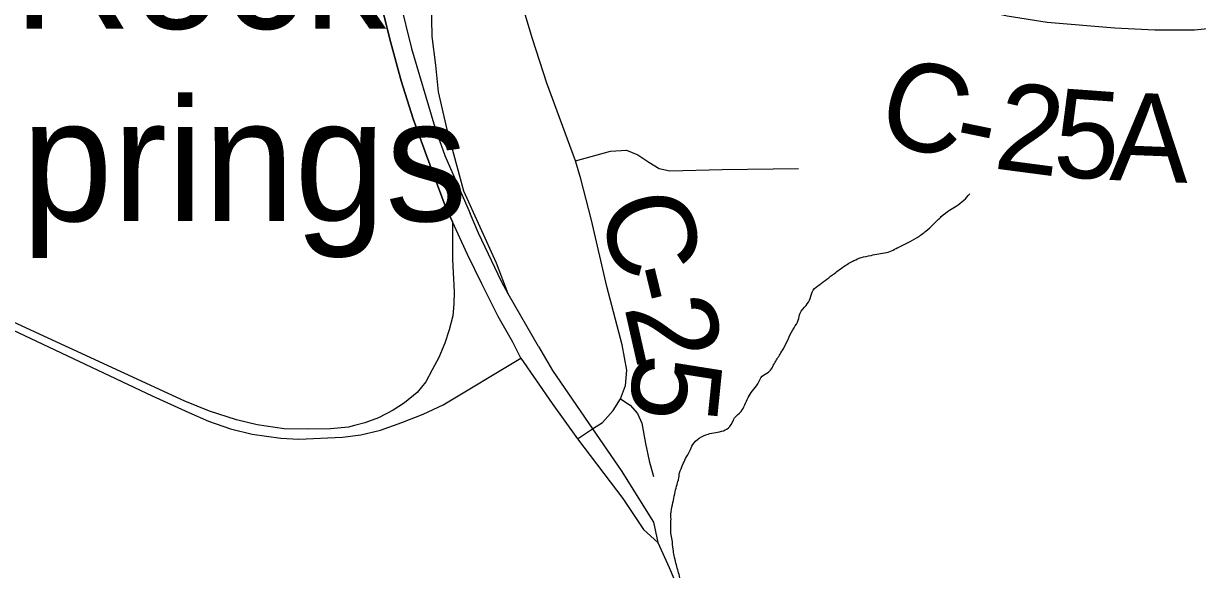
# Model space of a CAD drawing. Extents: x -20.2 to 34, y 0 to 22.
# Drawn here: x 5.177 to 5.935, y 15.58 to 15.933 of the extents above; entities that cross this region are included whole.
import ezdxf

# ---------------------------------------------------------------- set-up
doc = ezdxf.new("R2010")
doc.units = 0
for name, color, linetype in [('GM_X_County_Road', 7, 'Continuous'), ('GM_X_County_Road_Text', 7, 'Continuous'), ('GM_X_Interchange_Ramps', 7, 'Continuous'), ('GM_X_Minor_River', 7, 'Continuous'), ('GM_X_State_Route', 7, 'Continuous'), ('GM_X_Township_Road', 7, 'Continuous'), ('GM_X_Unincorporated_Text', 7, 'Continuous'), ('GM_X_US_Route', 7, 'Continuous')]:
    doc.layers.add(name, color=color, linetype=linetype)

msp = doc.modelspace()

# ---------------------------------------------------------------- linework, layer by layer
at = {"layer": 'GM_X_County_Road'}
for points in [[(5.75523, 15.95181), (5.77883, 15.94516), (5.81245, 15.93751), (5.8382, 15.93346), (5.88202, 15.92985), (5.8949, 15.92921), (5.90776, 15.92857), (5.9333, 15.92857), (5.9567, 15.93091), (5.97393, 15.93495), (6.04638, 15.95554)], [(5.53502, 15.66458), (5.54482, 15.67097), (5.55116, 15.67512), (5.55818, 15.68291), (5.56285, 15.69044), (5.56597, 15.69903), (5.56701, 15.7089), (5.5639, 15.72527), (5.55403, 15.76293), (5.54415, 15.80557), (5.53713, 15.83234), (5.53375, 15.84403), (5.51528, 15.89407), (5.50607, 15.92261), (5.50054, 15.94048)]]:
    msp.add_lwpolyline(points, dxfattribs=at)
at = {"layer": 'GM_X_Interchange_Ramps'}
msp.add_lwpolyline([(5.49038, 15.75812), (5.4828, 15.77801), (5.46179, 15.82446), (5.4509, 15.8641), (5.44535, 15.88847), (5.44363, 15.90567), (5.44133, 15.92417), (5.44076, 15.94714), (5.44092, 15.96778), (5.44274, 15.99016), (5.44484, 16.01367), (5.44575, 16.02546)], dxfattribs=at)
at = {"layer": 'GM_X_Minor_River'}
for points in [[(5.60098, 15.64268), (5.60292, 15.64761), (5.60485, 15.65176), (5.60754, 15.65668), (5.60947, 15.66084), (5.61367, 15.66498), (5.61938, 15.66759), (5.62926, 15.66979), (5.63346, 15.67242), (5.63654, 15.67809), (5.64074, 15.68223), (5.64305, 15.68639), (5.64805, 15.69546), (5.6515, 15.69999), (5.6542, 15.7049), (5.65839, 15.70753), (5.66261, 15.71395), (5.66645, 15.71999), (5.66876, 15.72414), (5.67493, 15.73624), (5.67762, 15.74116), (5.67879, 15.7457), (5.68263, 15.75061), (5.68532, 15.75514), (5.68725, 15.76044), (5.69146, 15.7642), (5.69603, 15.76758), (5.701, 15.77134), (5.7071, 15.77585), (5.71358, 15.77959), (5.71815, 15.78146), (5.72461, 15.78292), (5.72955, 15.78402), (5.73449, 15.78474), (5.74287, 15.78847), (5.7482, 15.79109), (5.7543, 15.79446), (5.76002, 15.79859), (5.76499, 15.80311), (5.76996, 15.808), (5.7753, 15.81213), (5.77949, 15.81476), (5.78446, 15.81852), (5.78828, 15.82266)], [(5.75291, 15.15939), (5.74953, 15.16435), (5.74087, 15.17315), (5.73824, 15.17735), (5.73486, 15.18193), (5.73187, 15.18727), (5.72735, 15.193), (5.72323, 15.1991), (5.72022, 15.2033), (5.71685, 15.20826), (5.71423, 15.2136), (5.71237, 15.21817), (5.71013, 15.22312), (5.70752, 15.22998), (5.70566, 15.23455), (5.70342, 15.23988), (5.70194, 15.24483), (5.7016, 15.24939), (5.70201, 15.25394), (5.70243, 15.25925), (5.70284, 15.26342), (5.70365, 15.27025), (5.70482, 15.27479), (5.70562, 15.27972), (5.70755, 15.28389), (5.70797, 15.28882), (5.70724, 15.29376), (5.70425, 15.29986), (5.69974, 15.30482), (5.69483, 15.3079), (5.68991, 15.31022), (5.68386, 15.31254), (5.67894, 15.31448), (5.67365, 15.31756), (5.66875, 15.32177), (5.66499, 15.32636), (5.66313, 15.33131), (5.66165, 15.33587), (5.65978, 15.34044), (5.65792, 15.34539), (5.65644, 15.34996), (5.65533, 15.35414), (5.65423, 15.35871), (5.65275, 15.36403), (5.65165, 15.36898), (5.65093, 15.3743), (5.65021, 15.37886), (5.6491, 15.38304), (5.64838, 15.3876), (5.64728, 15.39255), (5.6458, 15.39863), (5.6447, 15.40282), (5.64321, 15.40738), (5.64249, 15.41232), (5.64214, 15.4165), (5.64142, 15.42068), (5.64069, 15.42525), (5.63886, 15.43361), (5.63664, 15.44084), (5.63553, 15.44503), (5.63406, 15.45149), (5.63221, 15.45758), (5.63, 15.46671), (5.62814, 15.47166), (5.62742, 15.47698), (5.62594, 15.48116), (5.62483, 15.48535), (5.62412, 15.49105), (5.62263, 15.49524), (5.62115, 15.50094), (5.61967, 15.50551), (5.61856, 15.50969), (5.61708, 15.51426), (5.61598, 15.51882), (5.61375, 15.52453), (5.61302, 15.52871), (5.61004, 15.53595), (5.60893, 15.54013), (5.60821, 15.5447), (5.60636, 15.55192), (5.60526, 15.55611), (5.6034, 15.56143), (5.60268, 15.56638), (5.60158, 15.5717), (5.60085, 15.57588), (5.59864, 15.58425), (5.59754, 15.58919), (5.59681, 15.59337), (5.5961, 15.59945), (5.59537, 15.60363), (5.59544, 15.61274), (5.59548, 15.6173), (5.59666, 15.62336), (5.59784, 15.62904), (5.59902, 15.63397), (5.60019, 15.63814), (5.60098, 15.64268)]]:
    msp.add_spline(points, degree=3, dxfattribs=at)
at = {"layer": 'GM_X_State_Route'}
for points in [[(5.4332, 15.85923), (5.42891, 15.87114), (5.42133, 15.89552), (5.41467, 15.92013), (5.40903, 15.94217), (5.40544, 15.95858), (5.39319, 16.03068), (5.39075, 16.045), (5.38875, 16.0602)], [(5.45441, 15.8045), (5.44954, 15.81501), (5.43749, 15.84732), (5.4332, 15.85923)], [(5.49853, 15.71665), (5.49331, 15.72691), (5.48379, 15.74352), (5.47338, 15.76451), (5.46415, 15.78348), (5.45441, 15.8045)], [(5.50998, 15.72423), (5.49038, 15.75812), (5.486, 15.76597), (5.47127, 15.79731), (5.46575, 15.80998)], [(5.12688, 15.75529), (5.2604, 15.69228), (5.28423, 15.68152), (5.29696, 15.67596), (5.31099, 15.67106), (5.32504, 15.66747), (5.34364, 15.66486), (5.35507, 15.66421), (5.38347, 15.66551), (5.39522, 15.66715), (5.40795, 15.67009), (5.42167, 15.67498), (5.43553, 15.68037), (5.44844, 15.68641), (5.49853, 15.71665)], [(5.50998, 15.72423), (5.51898, 15.70865), (5.54482, 15.67097), (5.56332, 15.64399), (5.58417, 15.61069), (5.58697, 15.59754)], [(5.49853, 15.71665), (5.5187, 15.68728), (5.53502, 15.66458)], [(5.53502, 15.66458), (5.56438, 15.62593), (5.57776, 15.60593), (5.58697, 15.59754)], [(5.58697, 15.59754), (5.59436, 15.58159), (5.60094, 15.56581), (5.6062, 15.55052), (5.61196, 15.52997), (5.61689, 15.50892), (5.63094, 15.42707), (5.63429, 15.40897), (5.64013, 15.38613), (5.64376, 15.37025), (5.64973, 15.35079), (5.65586, 15.33217)]]:
    msp.add_lwpolyline(points, dxfattribs=at)
at = {"layer": 'GM_X_Township_Road'}
for points in [[(5.53375, 15.84403), (5.55636, 15.85027), (5.56676, 15.85079), (5.57395, 15.84793), (5.58118, 15.84304), (5.58777, 15.839), (5.59458, 15.8375), (5.62841, 15.83836), (5.67778, 15.83901)], [(5.56285, 15.69044), (5.56909, 15.68629), (5.57377, 15.68083), (5.57663, 15.67459), (5.57897, 15.6616), (5.58131, 15.65043), (5.58417, 15.64029)]]:
    msp.add_lwpolyline(points, dxfattribs=at)
at = {"layer": 'GM_X_US_Route'}
for points in [[(5.32948, 16.4963), (5.33321, 16.47263), (5.33614, 16.45673), (5.35628, 16.33081), (5.36333, 16.28673), (5.38001, 16.19003), (5.40354, 16.04385), (5.40604, 16.02948), (5.42042, 15.94697), (5.42784, 15.91649), (5.44228, 15.86788), (5.44498, 15.86017)], [(5.38875, 16.0602), (5.39075, 16.045), (5.39319, 16.03068), (5.40544, 15.95858), (5.40903, 15.94217), (5.41467, 15.92013), (5.42133, 15.89552), (5.42891, 15.87114), (5.4332, 15.85923)], [(5.4332, 15.85923), (5.43749, 15.84732), (5.44954, 15.81501), (5.45441, 15.8045)], [(5.44498, 15.86017), (5.44949, 15.84732), (5.46575, 15.80998)], [(5.45441, 15.8045), (5.45433, 15.78026), (5.45554, 15.75933), (5.45532, 15.75144), (5.45464, 15.74399), (5.45216, 15.73498), (5.44946, 15.72619), (5.44563, 15.71695), (5.44135, 15.70905), (5.43706, 15.70139), (5.43156, 15.6945), (5.42334, 15.68776), (5.4161, 15.68299), (5.40657, 15.67806), (5.39769, 15.67494), (5.3911, 15.67316)], [(5.3911, 15.67316), (5.38733, 15.67215), (5.37566, 15.671), (5.3607, 15.67067), (5.34574, 15.671), (5.32831, 15.67362), (5.31483, 15.67675), (5.29757, 15.68234), (5.28162, 15.68892), (5.16818, 15.74119)]]:
    msp.add_lwpolyline(points, dxfattribs=at)

# ---------------------------------------------------------------- texts
at = {"layer": 'GM_X_County_Road_Text'}
for s, rotation, p in [('C', 343.88358, (5.72603, 15.85876)), ('2', 352.50083, (5.80285, 15.83921)), ('5', 355.86605, (5.84117, 15.83427)), ('A', 357.82321, (5.8782, 15.83163)), ('-', 348.4062, (5.77562, 15.84463)), ('C', 283.99842, (5.54853, 15.81684)), ('-', 283.71777, (5.55972, 15.77197)), ('2', 282.78408, (5.56515, 15.74975)), ('5', 264.20447, (5.57253, 15.72072))]:
    msp.add_text(s, height=0.05682, rotation=rotation, dxfattribs=at).set_placement(p)
at = {"layer": 'GM_X_Unincorporated_Text'}
for s, p in [('Rock', (5.17083, 15.92922)), ('Springs', (5.10583, 15.80505))]:
    msp.add_text(s, height=0.078977, rotation=0.00001, dxfattribs=at).set_placement(p)

doc.saveas('drawing.dxf')
